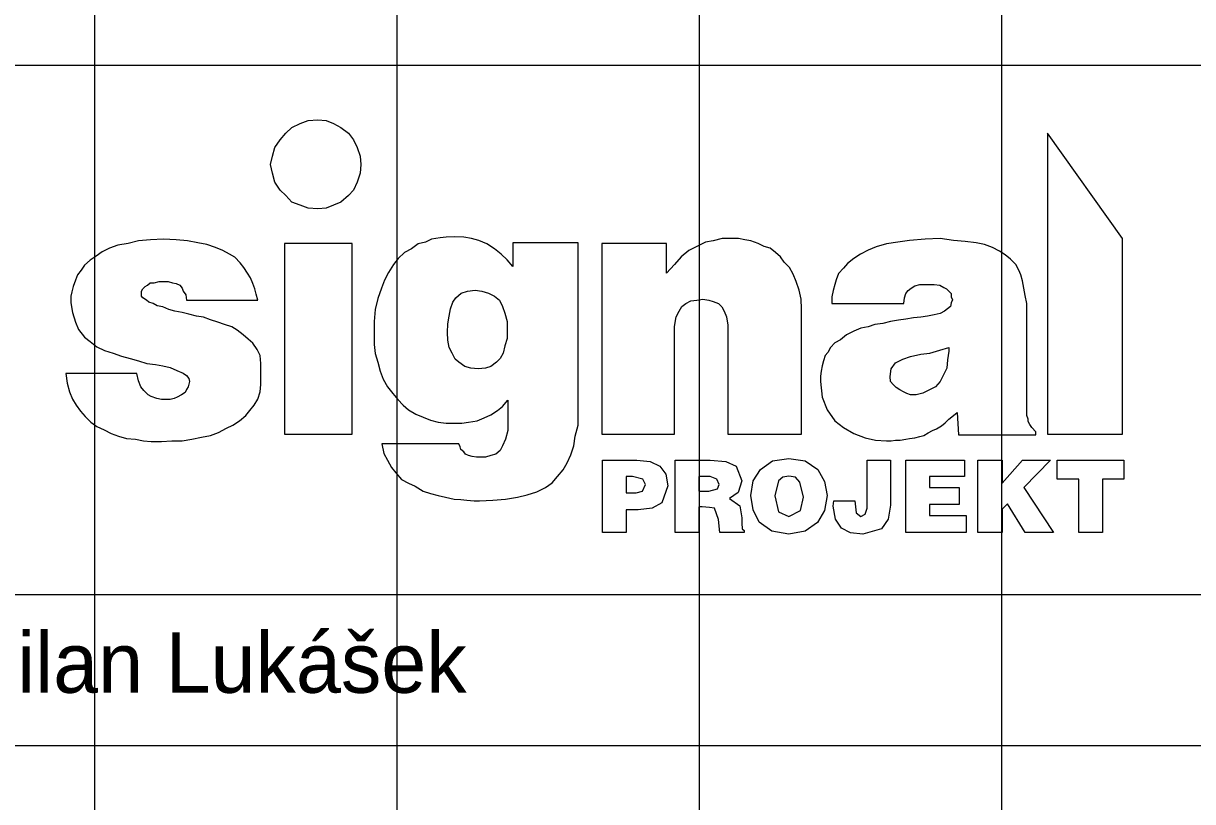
# Model space of a CAD drawing. Extents: x -1442 to 8065, y -772 to 6486.
# Drawn here: x 2542.64 to 2581.32, y 598.15 to 623.88 of the extents above; entities that cross this region are included whole.
import ezdxf

# ---------------------------------------------------------------- set-up
doc = ezdxf.new("R2010")
doc.units = 0
for name, color, linetype in [('Info o rozpiskách', 7, 'Continuous'), ('popis', 7, 'Continuous'), ('Rozpiska_pole_6', 7, 'Continuous')]:
    doc.layers.add(name, color=color, linetype=linetype)

msp = doc.modelspace()

# ---------------------------------------------------------------- linework, layer by layer
for p, q in [((2545, 659), (2545, 569)), ((2555, 659), (2555, 569)), ((2565, 659), (2565, 569)), ((2575, 659), (2575, 569))]:
    msp.add_line(p, q)
at = {"layer": 'Info o rozpiskách'}
for points in [[(2552.382, 620.697), (2552.662, 620.678), (2552.903, 620.578), (2553.143, 620.437), (2553.403, 620.257), (2553.563, 620.037), (2553.684, 619.776), (2553.784, 619.496), (2553.804, 619.215), (2553.784, 618.935), (2553.684, 618.634), (2553.563, 618.374), (2553.403, 618.194), (2553.143, 617.973), (2552.903, 617.873), (2552.662, 617.773), (2552.382, 617.753), (2552.061, 617.773), (2551.801, 617.873), (2551.52, 617.973), (2551.32, 618.194), (2551.14, 618.374), (2550.959, 618.634), (2550.879, 618.935), (2550.819, 619.215), (2550.879, 619.496), (2550.959, 619.776), (2551.14, 620.037), (2551.32, 620.257), (2551.52, 620.437), (2551.801, 620.578), (2552.061, 620.678), (2552.382, 620.697)], [(2561.797, 609.44), (2562.939, 609.44), (2563.379, 609.399), (2563.7, 609.239), (2563.9, 608.978), (2563.96, 608.598), (2563.76, 608.037), (2563.439, 607.856), (2562.979, 607.797), (2562.578, 607.797), (2562.578, 607.055), (2561.797, 607.055), (2561.797, 609.44)], [(2564.201, 609.44), (2565.363, 609.44), (2565.883, 609.399), (2566.224, 609.239), (2566.404, 608.758), (2566.284, 608.378), (2566.004, 608.177), (2566.344, 607.937), (2566.404, 607.536), (2566.404, 607.356), (2566.424, 607.175), (2566.485, 607.115), (2566.485, 607.055), (2565.683, 607.055), (2565.643, 607.476), (2565.503, 607.856), (2565.342, 607.877), (2565.102, 607.897), (2564.982, 607.897), (2564.982, 607.055), (2564.201, 607.055), (2564.201, 609.44)], [(2567.967, 609.499), (2568.508, 609.419), (2568.929, 609.139), (2569.149, 608.738), (2569.229, 608.278), (2569.149, 607.777), (2568.908, 607.376), (2568.508, 607.096), (2567.967, 606.996), (2567.406, 607.096), (2566.985, 607.396), (2566.785, 607.797), (2566.705, 608.278), (2566.785, 608.758), (2567.025, 609.139), (2567.426, 609.419), (2567.967, 609.499)], [(2570.55, 609.44), (2571.332, 609.44), (2571.332, 607.957), (2571.251, 607.496), (2571.031, 607.175), (2570.41, 606.996), (2570.009, 607.036), (2569.709, 607.196), (2569.509, 607.496), (2569.428, 607.917), (2569.448, 608.097), (2570.15, 608.097), (2570.19, 607.696), (2570.35, 607.577), (2570.49, 607.656), (2570.55, 607.856), (2570.55, 609.44)], [(2571.832, 609.44), (2573.776, 609.44), (2573.776, 608.899), (2572.613, 608.899), (2572.613, 608.538), (2573.595, 608.538), (2573.595, 607.977), (2572.613, 607.977), (2572.613, 607.616), (2573.835, 607.616), (2573.835, 607.055), (2571.832, 607.055), (2571.832, 609.44)], [(2574.216, 609.44), (2575.017, 609.44), (2575.017, 608.678), (2575.698, 609.44), (2576.62, 609.44), (2575.739, 608.538), (2576.72, 607.055), (2575.779, 607.055), (2575.198, 607.997), (2575.017, 607.817), (2575.017, 607.055), (2574.216, 607.055), (2574.216, 609.44)], [(2576.841, 609.44), (2579.044, 609.44), (2579.044, 608.818), (2578.343, 608.818), (2578.343, 607.055), (2577.561, 607.055), (2577.561, 608.818), (2576.841, 608.818), (2576.841, 609.44)], [(2562.578, 608.899), (2562.578, 608.358), (2562.919, 608.358), (2563.119, 608.418), (2563.219, 608.638), (2563.139, 608.818), (2562.798, 608.899), (2562.578, 608.899)], [(2564.982, 608.899), (2564.982, 608.418), (2565.323, 608.418), (2565.603, 608.497), (2565.663, 608.638), (2565.583, 608.818), (2565.363, 608.899), (2564.982, 608.899)], [(2567.967, 608.918), (2567.767, 608.878), (2567.626, 608.758), (2567.506, 608.258), (2567.626, 607.737), (2567.967, 607.577), (2568.348, 607.777), (2568.448, 608.218), (2568.327, 608.718), (2568.188, 608.878), (2567.967, 608.918)]]:
    msp.add_lwpolyline(points, dxfattribs=at)
at = {"layer": 'popis'}
for points in [[(2576.52, 620.257), (2576.52, 610.3), (2579.004, 610.3), (2579.004, 616.771), (2576.52, 620.257)], [(2548.034, 614.728), (2550.398, 614.728), (2550.338, 614.928), (2550.298, 615.109), (2550.238, 615.288), (2550.158, 615.469), (2550.057, 615.629), (2549.938, 615.81), (2549.818, 615.97), (2549.637, 616.15), (2549.457, 616.25), (2549.237, 616.371), (2548.996, 616.471), (2548.716, 616.571), (2548.415, 616.631), (2548.075, 616.691), (2547.694, 616.731), (2547.274, 616.751), (2546.853, 616.731), (2546.452, 616.691), (2546.112, 616.611), (2545.771, 616.551), (2545.49, 616.451), (2545.25, 616.331), (2545.05, 616.19), (2544.849, 616.05), (2544.669, 615.89), (2544.549, 615.729), (2544.428, 615.569), (2544.369, 615.389), (2544.288, 615.188), (2544.249, 615.009), (2544.208, 614.868), (2544.208, 614.647), (2544.268, 614.327), (2544.369, 614.007), (2544.469, 613.766), (2544.669, 613.506), (2544.849, 613.366), (2545.069, 613.185), (2545.33, 613.065), (2545.61, 612.985), (2545.891, 612.885), (2546.172, 612.805), (2546.452, 612.725), (2546.732, 612.644), (2547.013, 612.605), (2547.253, 612.565), (2547.494, 612.504), (2547.714, 612.404), (2547.934, 612.324), (2548.034, 612.244), (2548.115, 612.144), (2548.135, 612.044), (2548.094, 611.863), (2548.034, 611.783), (2547.994, 611.683), (2547.874, 611.603), (2547.734, 611.522), (2547.634, 611.483), (2547.494, 611.443), (2547.353, 611.443), (2547.213, 611.443), (2547.053, 611.483), (2546.872, 611.543), (2546.772, 611.603), (2546.632, 611.743), (2546.532, 611.863), (2546.452, 612.063), (2546.392, 612.304), (2544.048, 612.304), (2544.088, 611.984), (2544.168, 611.703), (2544.268, 611.462), (2544.388, 611.262), (2544.529, 611.062), (2544.689, 610.881), (2544.869, 610.702), (2545.069, 610.561), (2545.31, 610.441), (2545.55, 610.321), (2545.791, 610.241), (2546.051, 610.161), (2546.352, 610.14), (2546.612, 610.08), (2546.872, 610.06), (2547.213, 610.06), (2547.554, 610.08), (2547.894, 610.08), (2548.215, 610.14), (2548.535, 610.2), (2548.835, 610.261), (2549.096, 610.361), (2549.357, 610.501), (2549.577, 610.602), (2549.797, 610.741), (2549.998, 610.922), (2550.138, 611.082), (2550.278, 611.262), (2550.398, 611.462), (2550.478, 611.703), (2550.499, 611.943), (2550.499, 612.184), (2550.499, 612.244), (2550.499, 612.304), (2550.499, 612.364), (2550.499, 612.424), (2550.499, 612.504), (2550.499, 612.565), (2550.499, 612.605), (2550.499, 612.644), (2550.478, 612.905), (2550.378, 613.105), (2550.238, 613.306), (2550.078, 613.446), (2549.918, 613.586), (2549.718, 613.746), (2549.537, 613.847), (2549.297, 613.927), (2549.076, 614.007), (2548.835, 614.087), (2548.596, 614.167), (2548.375, 614.207), (2548.115, 614.267), (2547.894, 614.327), (2547.654, 614.368), (2547.453, 614.428), (2547.253, 614.507), (2547.073, 614.547), (2546.933, 614.628), (2546.793, 614.668), (2546.712, 614.728), (2546.593, 614.808), (2546.552, 614.868), (2546.552, 614.948), (2546.552, 615.028), (2546.593, 615.109), (2546.672, 615.188), (2546.753, 615.229), (2546.832, 615.309), (2546.973, 615.309), (2547.133, 615.349), (2547.274, 615.349), (2547.434, 615.349), (2547.574, 615.309), (2547.694, 615.288), (2547.814, 615.229), (2547.894, 615.128), (2547.934, 615.028), (2548.015, 614.908), (2548.034, 614.728)], [(2551.28, 616.611), (2551.28, 610.3), (2553.523, 610.3), (2553.523, 616.611), (2551.28, 616.611)], [(2558.832, 616.631), (2558.832, 615.85), (2558.651, 616.07), (2558.451, 616.25), (2558.231, 616.431), (2557.97, 616.591), (2557.71, 616.711), (2557.47, 616.771), (2557.209, 616.812), (2556.909, 616.831), (2556.628, 616.812), (2556.428, 616.791), (2556.148, 616.751), (2555.947, 616.651), (2555.707, 616.591), (2555.487, 616.431), (2555.246, 616.31), (2555.046, 616.11), (2554.885, 615.91), (2554.725, 615.65), (2554.585, 615.389), (2554.485, 615.128), (2554.365, 614.788), (2554.285, 614.428), (2554.244, 614.027), (2554.244, 613.606), (2554.244, 613.265), (2554.285, 612.965), (2554.365, 612.684), (2554.445, 612.384), (2554.545, 612.124), (2554.685, 611.863), (2554.866, 611.643), (2555.026, 611.443), (2555.206, 611.262), (2555.387, 611.102), (2555.626, 610.962), (2555.867, 610.862), (2556.107, 610.762), (2556.368, 610.702), (2556.628, 610.661), (2556.909, 610.661), (2557.15, 610.661), (2557.37, 610.702), (2557.65, 610.741), (2557.891, 610.841), (2558.111, 610.941), (2558.331, 611.082), (2558.491, 611.222), (2558.672, 611.422), (2558.672, 610.841), (2558.672, 610.421), (2558.591, 610.14), (2558.491, 609.92), (2558.411, 609.76), (2558.271, 609.64), (2558.111, 609.6), (2557.931, 609.54), (2557.731, 609.54), (2557.63, 609.54), (2557.49, 609.559), (2557.37, 609.6), (2557.269, 609.64), (2557.209, 609.719), (2557.109, 609.8), (2557.089, 609.88), (2557.049, 609.98), (2554.505, 609.98), (2554.565, 609.659), (2554.685, 609.44), (2554.825, 609.199), (2554.966, 609.019), (2555.146, 608.799), (2555.387, 608.678), (2555.607, 608.578), (2555.867, 608.418), (2556.107, 608.337), (2556.368, 608.278), (2556.609, 608.218), (2556.889, 608.158), (2557.109, 608.137), (2557.31, 608.117), (2557.55, 608.097), (2557.731, 608.097), (2558.171, 608.117), (2558.591, 608.158), (2558.992, 608.218), (2559.313, 608.297), (2559.633, 608.397), (2559.914, 608.538), (2560.134, 608.698), (2560.314, 608.899), (2560.495, 609.119), (2560.635, 609.359), (2560.755, 609.619), (2560.855, 609.92), (2560.895, 610.241), (2560.995, 610.602), (2560.995, 610.982), (2560.995, 611.422), (2560.995, 616.631), (2558.832, 616.631)], [(2561.776, 616.611), (2561.776, 610.3), (2564.181, 610.3), (2564.181, 613.526), (2564.181, 613.866), (2564.241, 614.187), (2564.341, 614.368), (2564.421, 614.528), (2564.561, 614.628), (2564.722, 614.708), (2564.922, 614.728), (2565.122, 614.768), (2565.323, 614.728), (2565.463, 614.688), (2565.643, 614.628), (2565.744, 614.507), (2565.823, 614.368), (2565.904, 614.187), (2565.944, 613.906), (2565.944, 613.626), (2565.944, 610.3), (2568.388, 610.3), (2568.388, 614.107), (2568.388, 614.447), (2568.367, 614.768), (2568.307, 615.068), (2568.207, 615.349), (2568.107, 615.59), (2567.986, 615.81), (2567.807, 615.99), (2567.686, 616.171), (2567.526, 616.31), (2567.346, 616.451), (2567.145, 616.51), (2566.945, 616.611), (2566.705, 616.691), (2566.504, 616.731), (2566.304, 616.771), (2566.064, 616.771), (2565.763, 616.771), (2565.463, 616.691), (2565.202, 616.651), (2564.922, 616.51), (2564.661, 616.371), (2564.401, 616.171), (2564.181, 615.91), (2563.92, 615.629), (2563.92, 616.611), (2561.776, 616.611)], [(2569.388, 614.628), (2571.772, 614.628), (2571.792, 614.808), (2571.832, 614.948), (2571.913, 615.049), (2572.013, 615.128), (2572.133, 615.209), (2572.293, 615.249), (2572.433, 615.249), (2572.594, 615.249), (2572.773, 615.249), (2572.954, 615.229), (2573.094, 615.149), (2573.175, 615.109), (2573.254, 615.028), (2573.335, 614.948), (2573.335, 614.848), (2573.375, 614.748), (2573.335, 614.647), (2573.315, 614.528), (2573.214, 614.447), (2573.114, 614.368), (2572.975, 614.287), (2572.773, 614.247), (2572.553, 614.207), (2572.333, 614.167), (2572.092, 614.147), (2571.832, 614.107), (2571.592, 614.066), (2571.332, 614.027), (2571.071, 613.966), (2570.81, 613.927), (2570.59, 613.847), (2570.35, 613.806), (2570.11, 613.706), (2569.869, 613.586), (2569.669, 613.426), (2569.488, 613.325), (2569.348, 613.165), (2569.249, 613.005), (2569.169, 612.905), (2569.108, 612.725), (2569.069, 612.565), (2569.029, 612.384), (2569.008, 612.224), (2569.008, 612.044), (2569.069, 611.522), (2569.229, 611.102), (2569.488, 610.741), (2569.769, 610.521), (2570.11, 610.321), (2570.49, 610.181), (2570.831, 610.1), (2571.191, 610.08), (2571.351, 610.08), (2571.492, 610.1), (2571.652, 610.1), (2571.832, 610.14), (2571.953, 610.161), (2572.133, 610.181), (2572.293, 610.221), (2572.433, 610.261), (2572.573, 610.341), (2572.714, 610.421), (2572.854, 610.481), (2573.014, 610.581), (2573.135, 610.681), (2573.254, 610.802), (2573.415, 610.922), (2573.535, 611.022), (2573.575, 610.281), (2576.139, 610.281), (2576.139, 610.381), (2575.999, 610.521), (2575.939, 610.621), (2575.879, 610.721), (2575.879, 610.802), (2575.839, 610.922), (2575.839, 611.002), (2575.839, 611.122), (2575.839, 611.282), (2575.839, 614.368), (2575.839, 614.628), (2575.779, 614.888), (2575.739, 615.128), (2575.698, 615.369), (2575.638, 615.569), (2575.578, 615.729), (2575.478, 615.91), (2575.298, 616.09), (2575.117, 616.231), (2574.938, 616.35), (2574.697, 616.471), (2574.436, 616.571), (2574.156, 616.631), (2573.795, 616.671), (2573.415, 616.711), (2572.975, 616.771), (2572.473, 616.751), (2571.953, 616.711), (2571.572, 616.651), (2571.191, 616.591), (2570.851, 616.491), (2570.59, 616.391), (2570.33, 616.25), (2570.11, 616.11), (2569.909, 615.95), (2569.769, 615.79), (2569.609, 615.609), (2569.529, 615.409), (2569.488, 615.249), (2569.428, 615.049), (2569.388, 614.848), (2569.388, 614.628)], [(2557.59, 615.068), (2557.81, 615.028), (2558.031, 614.968), (2558.231, 614.868), (2558.391, 614.728), (2558.491, 614.528), (2558.572, 614.307), (2558.651, 614.027), (2558.651, 613.726), (2558.651, 613.466), (2558.572, 613.225), (2558.512, 612.985), (2558.411, 612.805), (2558.291, 612.684), (2558.111, 612.544), (2557.931, 612.484), (2557.69, 612.465), (2557.45, 612.484), (2557.25, 612.544), (2557.049, 612.684), (2556.929, 612.785), (2556.829, 612.985), (2556.729, 613.165), (2556.688, 613.406), (2556.669, 613.666), (2556.688, 613.947), (2556.729, 614.207), (2556.769, 614.447), (2556.848, 614.668), (2556.949, 614.808), (2557.129, 614.968), (2557.329, 615.028), (2557.59, 615.068)], [(2573.254, 613.165), (2573.254, 613.146), (2573.254, 613.085), (2573.254, 613.046), (2573.214, 612.765), (2573.194, 612.484), (2573.094, 612.284), (2572.975, 612.044), (2572.814, 611.863), (2572.613, 611.763), (2572.393, 611.663), (2572.173, 611.603), (2571.992, 611.603), (2571.872, 611.643), (2571.753, 611.703), (2571.632, 611.763), (2571.512, 611.843), (2571.412, 611.943), (2571.332, 612.044), (2571.312, 612.204), (2571.351, 612.465), (2571.492, 612.665), (2571.732, 612.785), (2571.992, 612.865), (2572.333, 612.945), (2572.634, 612.985), (2572.954, 613.085), (2573.254, 613.165)]]:
    msp.add_lwpolyline(points, dxfattribs=at)
at = {"layer": 'Rozpiska_pole_6'}
for p, q in [((2430, 622.5), (2600, 622.5)), ((2430, 605), (2600, 605))]:
    msp.add_line(p, q, dxfattribs=at)
msp.add_lwpolyline([(2430, 640), (2600, 640), (2600, 600), (2430, 600)], close=True, dxfattribs=at)

# ---------------------------------------------------------------- texts
msp.add_text('Ing. Milan Lukášek', height=2, dxfattribs=at).set_placement((2535.009, 601.75))

doc.saveas('drawing.dxf')
